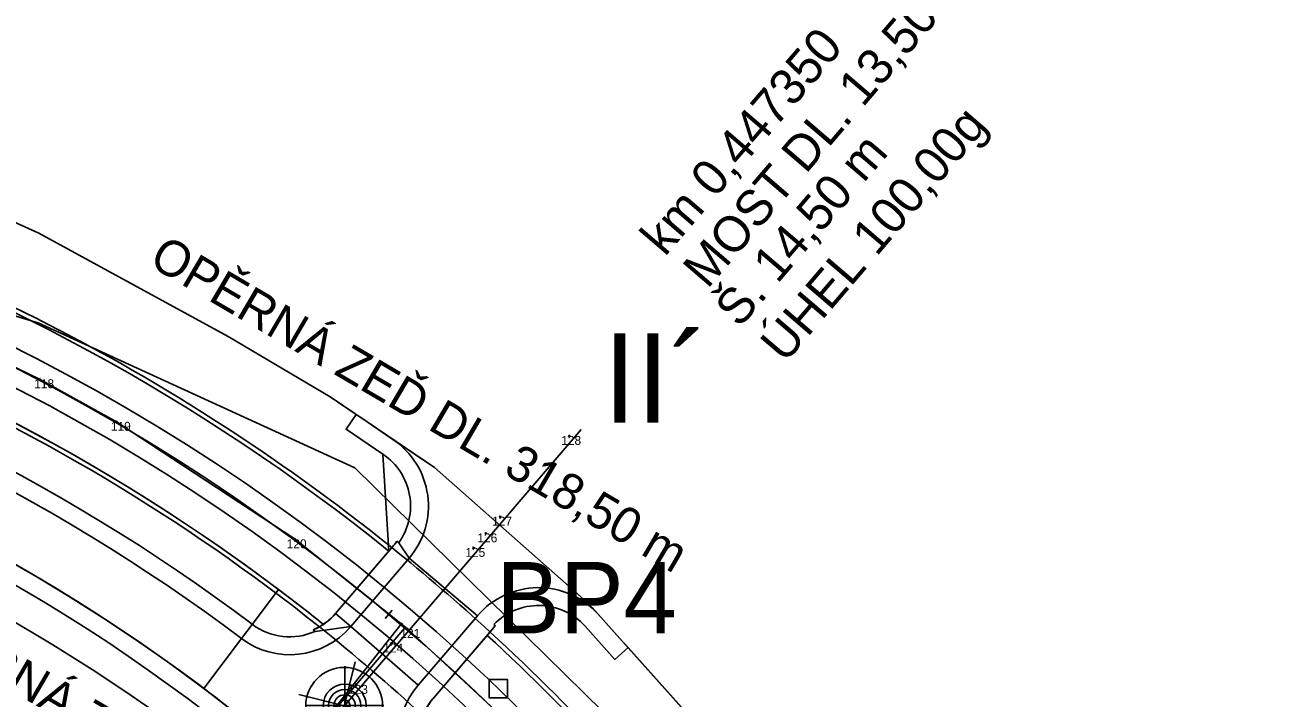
# Model space of a CAD drawing. Extents: x -606444 to -604546, y -1158114 to -1156869.
# Drawn here: x -605244.8 to -605105.4, y -1157184.6 to -1157109.2 of the extents above; entities that cross this region are included whole.
import ezdxf

# ---------------------------------------------------------------- set-up
doc = ezdxf.new("R2010")
doc.units = 0
for name, color, linetype in [('0_sondy', 7, 'Continuous'), ('B_CHOD', 7, 'Continuous'), ('B_TRAM', 7, 'Continuous'), ('B_VOZ', 7, 'Continuous'), ('B_ZELEN', 7, 'Continuous'), ('geofyzikální profily_předběžný GTP', 7, 'Continuous'), ('jádrové vrty_předběžný GTP', 7, 'Continuous'), ('korozní průzkum', 7, 'Continuous'), ('netisk', 7, 'Continuous'), ('netisk2', 7, 'Continuous'), ('NS_VB', 7, 'Continuous'), ('NS_VB_OBJ', 7, 'Continuous'), ('NS_VB_POP', 7, 'Continuous'), ('OSA', 7, 'Continuous'), ('OSAPOP', 7, 'Continuous'), ('podélný profil trasou tramvaje', 7, 'Continuous'), ('sondy současného průzkumu', 7, 'Continuous'), ('stabilitní profily_předběžný GTP', 7, 'Continuous')]:
    doc.layers.add(name, color=color, linetype=linetype)

# ---------------------------------------------------------------- blocks, each defined once
blk = doc.blocks.new('709')
for p, q in [((0, 2.2), (0, -2.2)), ((-2.2, 0), (2.2, 0))]:
    blk.add_line(p, q)
for radius in [1.2, 0.9, 0.6, 0.3]:
    blk.add_circle((0, 0), radius)
blk = doc.blocks.new('IG vrt podr')
at = {"layer": 'sondy současného průzkumu'}
for p, q in [((0.412, 1.649), (-0.418, -1.672)), ((-1.698, 0.422), (1.644, -0.408))]:
    blk.add_line(p, q, dxfattribs=at)
blk.add_circle((-0.002, 0.001), 1.434, dxfattribs=at)

msp = doc.modelspace()

# ---------------------------------------------------------------- linework, layer by layer
for p, q in [((-605243.13, -1157148.91), (-605243.23, -1157148.81)), ((-605243.13, -1157148.91), (-605243.23, -1157149.01)), ((-605243.13, -1157148.91), (-605243.03, -1157148.81)), ((-605243.13, -1157148.91), (-605243.03, -1157149.01)), ((-605234.53, -1157153.68), (-605234.63, -1157153.58)), ((-605234.53, -1157153.68), (-605234.63, -1157153.78)), ((-605234.53, -1157153.68), (-605234.43, -1157153.58)), ((-605234.53, -1157153.68), (-605234.43, -1157153.78)), ((-605183.79, -1157155.26), (-605183.89, -1157155.16)), ((-605183.79, -1157155.26), (-605183.69, -1157155.16)), ((-605183.79, -1157155.26), (-605183.89, -1157155.36)), ((-605183.79, -1157155.26), (-605183.69, -1157155.36)), ((-605191.53, -1157164.3), (-605191.63, -1157164.2)), ((-605191.53, -1157164.3), (-605191.63, -1157164.4)), ((-605191.53, -1157164.3), (-605191.43, -1157164.2)), ((-605191.53, -1157164.3), (-605191.43, -1157164.4)), ((-605193.15, -1157166.17), (-605193.25, -1157166.07)), ((-605193.15, -1157166.17), (-605193.25, -1157166.27)), ((-605193.15, -1157166.17), (-605193.05, -1157166.07)), ((-605193.15, -1157166.17), (-605193.05, -1157166.27)), ((-605214.51, -1157166.83), (-605214.61, -1157166.73)), ((-605214.51, -1157166.83), (-605214.61, -1157166.93)), ((-605214.51, -1157166.83), (-605214.41, -1157166.73)), ((-605214.51, -1157166.83), (-605214.41, -1157166.93)), ((-605194.53, -1157167.79), (-605194.63, -1157167.69)), ((-605194.53, -1157167.79), (-605194.43, -1157167.69)), ((-605194.53, -1157167.79), (-605194.63, -1157167.89)), ((-605194.53, -1157167.79), (-605194.43, -1157167.89)), ((-605201.93, -1157176.87), (-605202.03, -1157176.77)), ((-605201.93, -1157176.87), (-605202.03, -1157176.97)), ((-605201.93, -1157176.87), (-605201.83, -1157176.77)), ((-605201.93, -1157176.87), (-605201.83, -1157176.97)), ((-605203.73, -1157178.5), (-605203.83, -1157178.4)), ((-605203.73, -1157178.5), (-605203.83, -1157178.6)), ((-605203.73, -1157178.5), (-605203.63, -1157178.4)), ((-605203.73, -1157178.5), (-605203.63, -1157178.6)), ((-605207.68, -1157183.13), (-605207.78, -1157183.03)), ((-605207.68, -1157183.13), (-605207.58, -1157183.03)), ((-605207.68, -1157183.13), (-605207.78, -1157183.23)), ((-605207.68, -1157183.13), (-605207.58, -1157183.23))]:
    msp.add_line(p, q)
at = {"layer": 'B_CHOD'}
for points in [[(-605203.54, -1157155.64), (-605206.43, -1157153.69), (-605207.68, -1157152.85), (-605208.8, -1157154.51), (-605204.66, -1157157.3)], [(-605203.44, -1157167.49), (-605209.98, -1157175.14), (-605208.27, -1157176.6)], [(-605208.27, -1157176.6), (-605201.73, -1157168.96), (-605202.9, -1157167.21), (-605203.09, -1157167.05)], [(-605202.9, -1157167.21), (-605201.73, -1157168.96)], [(-605212.47, -1157176.97), (-605212.25, -1157177.14), (-605208.27, -1157176.6), (-605209.98, -1157175.14)], [(-605194.07, -1157175.39), (-605200.71, -1157183.15)], [(-605182.02, -1157176.56), (-605178.68, -1157180.28), (-605177.2, -1157178.94), (-605178.11, -1157177.92), (-605180.54, -1157175.22)], [(-605219.32, -1157176.35), (-605220.52, -1157177.94)], [(-605220.52, -1157177.94), (-605219.32, -1157176.35)], [(-605208.27, -1157176.6), (-605212.25, -1157177.14)], [(-605199, -1157184.61), (-605192.99, -1157177.59), (-605192.23, -1157176.7)], [(-605192.07, -1157176.52), (-605192.25, -1157176.35)]]:
    msp.add_lwpolyline(points, dxfattribs=at)
for centre, radius, start, end in [((-605345.26, -1157343.76), 209.5, 53.0471, 97.5799), ((-605345.26, -1157343.76), 207.5, 53.0471, 97.5799), ((-605345.26, -1157343.76), 200.5, 46.8415, 97.5799), ((-605345.26, -1157343.76), 198.5, 46.8415, 97.5799), ((-605208.57, -1157163.11), 9, 319.4626, 56.0176), ((-605208.57, -1157163.11), 7, 324.1224, 56.0176), ((-605208.57, -1157163.11), 6.75, 319.4626, 324.2325), ((-605187.23, -1157181.24), 9, 41.9382, 139.4626), ((-605187.23, -1157181.24), 7, 41.9382, 135.7827), ((-605215.1, -1157170.75), 6.75, 306.2266, 319.4658), ((-605215.11, -1157170.75), 9, 233.0471, 319.4626), ((-605215.11, -1157170.75), 7, 233.0471, 294.1), ((-605215.11, -1157170.75), 6.75, 292.9973, 306.2299), ((-605187.1, -1157181.08), 6.75, 137.3987, 139.4626), ((-605193.87, -1157189), 9, 139.4626, 225.6318)]:
    msp.add_arc(centre, radius, start, end, dxfattribs=at)
at = {"layer": 'B_TRAM'}
for p, q in [((-605209.98, -1157175.14), (-605203.99, -1157168.14)), ((-605192.99, -1157177.59), (-605199, -1157184.61))]:
    msp.add_line(p, q, dxfattribs=at)
for centre, radius, start, end in [((-605345.33, -1157343.85), 225.5, 51.1864, 92.2057), ((-605345.33, -1157343.85), 214.5, 51.3406, 92.204), ((-605215.1, -1157170.75), 6.75, 303.9373, 319.4658), ((-605345.33, -1157343.85), 225.5, 27.1946, 47.5015), ((-605193.87, -1157188.99), 6.75, 139.4591, 154.7431)]:
    msp.add_arc(centre, radius, start, end, dxfattribs=at)
at = {"layer": 'B_VOZ'}
for points in [[(-605180.54, -1157175.22), (-605181.54, -1157174.1), (-605198.87, -1157158.79), (-605203.54, -1157155.64)], [(-605203.54, -1157155.64), (-605203.54, -1157155.64)], [(-605201.73, -1157168.96), (-605208.27, -1157176.6), (-605200.71, -1157183.15), (-605194.07, -1157175.39), (-605201.73, -1157168.96)], [(-605201.73, -1157168.96), (-605194.07, -1157175.39)], [(-605200.71, -1157183.15), (-605208.27, -1157176.6)], [(-605220.52, -1157177.94), (-605224.73, -1157183.54)], [(-605224.73, -1157183.54), (-605220.52, -1157177.94)]]:
    msp.add_lwpolyline(points, dxfattribs=at)
for centre, radius, start, end in [((-605345.26, -1157343.76), 207.5, 53.0471, 97.5799), ((-605345.26, -1157343.76), 200.5, 53.0471, 97.5799), ((-605208.57, -1157163.11), 9, 319.4626, 56.0174), ((-605208.57, -1157163.11), 9, 56.0174, 56.0176), ((-605187.23, -1157181.24), 9, 41.9382, 139.4626), ((-605215.11, -1157170.75), 9, 233.0471, 319.4626), ((-605345.26, -1157343.76), 200.5, 45.6318, 53.0471), ((-605193.87, -1157189), 9, 139.4626, 225.6318)]:
    msp.add_arc(centre, radius, start, end, dxfattribs=at)
at = {"layer": 'B_ZELEN'}
for points in [[(-605203.99, -1157168.14), (-605204.66, -1157157.3), (-605208.8, -1157154.51), (-605207.68, -1157152.85), (-605210.59, -1157150.89), (-605221.99, -1157144.13), (-605243.23, -1157132.55), (-605253.62, -1157127.89), (-605260.44, -1157124.83), (-605265.07, -1157123.34), (-605269.63, -1157121.52), (-605278.31, -1157118.54), (-605290.81, -1157115.61), (-605306.23, -1157112.78), (-605315.84, -1157111.84), (-605328.25, -1157110.41), (-605344.82, -1157109.94), (-605357.9, -1157109.88), (-605354.01, -1157118.52)], [(-605204.66, -1157157.3), (-605203.99, -1157168.14), (-605203.44, -1157167.49)], [(-605203.09, -1157167.05), (-605202.9, -1157167.21)], [(-605216.38, -1157172.44), (-605219.32, -1157176.35)], [(-605219.32, -1157176.35), (-605216.38, -1157172.44)], [(-605212.25, -1157177.14), (-605212.47, -1157176.97)], [(-605192.23, -1157176.7), (-605192.99, -1157177.59)], [(-605192.25, -1157176.35), (-605192.07, -1157176.52)], [(-605144.76, -1157240.79), (-605133.95, -1157239.93), (-605143.53, -1157224.32), (-605151.31, -1157212.15), (-605159.56, -1157200.24), (-605168.04, -1157189.17), (-605177.2, -1157178.94), (-605178.68, -1157180.28), (-605182.02, -1157176.56)]]:
    msp.add_lwpolyline(points, dxfattribs=at)
for centre, radius, start, end in [((-605345.33, -1157343.85), 225.5, 51.1864, 92.2057), ((-605345.33, -1157343.85), 214.5, 53.0445, 92.204), ((-605345.26, -1157343.76), 209.5, 53.0471, 97.5799), ((-605345.26, -1157343.76), 198.5, 46.8415, 97.5799), ((-605345.97, -1157349.67), 200.33, 48.8336, 96.6948), ((-605208.57, -1157163.11), 7, 324.1224, 56.0176), ((-605208.57, -1157163.11), 6.75, 319.4626, 323.1301), ((-605208.57, -1157163.11), 6.75, 323.1301, 323.9726), ((-605208.57, -1157163.11), 6.75, 323.9726, 324.2325), ((-605345.33, -1157343.85), 214.5, 51.3406, 53.0445), ((-605187.23, -1157181.24), 7, 41.9382, 135.7827), ((-605215.11, -1157170.75), 7, 233.0471, 294.1), ((-605215.11, -1157170.75), 6.75, 292.9973, 303.9417), ((-605187.1, -1157181.08), 6.75, 137.3987, 139.4626), ((-605345.33, -1157343.85), 225.5, 27.1946, 47.5015)]:
    msp.add_arc(centre, radius, start, end, dxfattribs=at)
at = {"layer": 'geofyzikální profily_předběžný GTP'}
msp.add_lwpolyline([(-605670.78, -1157141.05), (-605656.02, -1157139.47), (-605613.88, -1157139.36), (-605584.8, -1157137.32), (-605531.41, -1157136.33), (-605491.56, -1157133.4), (-605482.07, -1157135.61), (-605438.78, -1157126.66), (-605383.23, -1157124.52), (-605352.34, -1157123.33), (-605321.95, -1157126), (-605284.14, -1157130.42), (-605243.3, -1157142.6), (-605207.83, -1157158.83), (-605179.98, -1157186.15), (-605165.29, -1157202.67), (-605149.23, -1157223.34), (-605135.07, -1157244.47), (-605115.92, -1157286.28), (-605103.22, -1157315.84), (-605095.33, -1157330.32), (-605036.97, -1157403.36), (-604999.08, -1157442.54), (-604970.8, -1157468.35)], dxfattribs=at)
at = {"layer": 'korozní průzkum'}
msp.add_lwpolyline([(-605192.77, -1157182.54), (-605190.69, -1157182.54), (-605190.69, -1157184.57), (-605192.77, -1157184.57)], close=True, dxfattribs=at)
at = {"layer": 'netisk'}
msp.add_line((-605202.52, -1157176.17), (-605211.11, -1157187.04), dxfattribs=at)
at = {"layer": 'netisk2'}
msp.add_line((-605211.04, -1157187.04), (-605202.23, -1157176.75), dxfattribs=at)
at = {"layer": 'NS_VB'}
for p, q in [((-605253.62, -1157127.89), (-605243.23, -1157132.55)), ((-605243.23, -1157132.55), (-605221.99, -1157144.13)), ((-605221.99, -1157144.13), (-605210.59, -1157150.89)), ((-605210.59, -1157150.89), (-605206.43, -1157153.69)), ((-605207.68, -1157152.85), (-605208.8, -1157154.51)), ((-605198.87, -1157158.79), (-605206.43, -1157153.69)), ((-605204.66, -1157157.3), (-605208.8, -1157154.51)), ((-605181.54, -1157174.1), (-605198.87, -1157158.79)), ((-605203.44, -1157167.49), (-605209.98, -1157175.14)), ((-605203.09, -1157167.05), (-605202.9, -1157167.21)), ((-605201.73, -1157168.96), (-605208.27, -1157176.6)), ((-605181.54, -1157174.1), (-605178.11, -1157177.92)), ((-605194.07, -1157175.39), (-605200.71, -1157183.15)), ((-605212.25, -1157177.14), (-605212.47, -1157176.97)), ((-605192.23, -1157176.7), (-605199, -1157184.61)), ((-605192.25, -1157176.35), (-605192.07, -1157176.52)), ((-605182.02, -1157176.56), (-605178.68, -1157180.28)), ((-605178.11, -1157177.92), (-605168.04, -1157189.17)), ((-605177.2, -1157178.94), (-605178.68, -1157180.28))]:
    msp.add_line(p, q, dxfattribs=at)
for centre, radius, start, end in [((-605345.33, -1157343.85), 225.5, 51.1864, 92.2057), ((-605345.33, -1157343.85), 214.5, 51.3406, 92.204), ((-605345.26, -1157343.76), 209.5, 53.0471, 97.5799), ((-605345.26, -1157343.76), 207.5, 53.0471, 97.5799), ((-605345.26, -1157343.76), 200.5, 16.4017, 97.5799), ((-605345.26, -1157343.76), 198.5, 46.8415, 97.5799), ((-605345.97, -1157349.67), 200.33, 48.8336, 96.6948), ((-605208.57, -1157163.11), 9, 319.4626, 56.0176), ((-605208.57, -1157163.11), 7, 324.1224, 56.0176), ((-605208.57, -1157163.11), 6.75, 319.4626, 324.2325), ((-605187.23, -1157181.24), 9, 41.9382, 139.4626), ((-605187.23, -1157181.24), 7, 41.9382, 135.7827), ((-605215.11, -1157170.75), 6.75, 292.9973, 319.4626), ((-605215.11, -1157170.75), 9, 233.0471, 319.4626), ((-605215.11, -1157170.75), 7, 233.0471, 294.1), ((-605187.1, -1157181.08), 6.75, 137.3987, 139.4626), ((-605345.33, -1157343.85), 225.5, 27.1946, 47.5015), ((-605193.87, -1157189), 9, 139.4626, 225.6318), ((-605193.87, -1157189), 6.75, 139.4626, 165.6816)]:
    msp.add_arc(centre, radius, start, end, dxfattribs=at)
at = {"layer": 'NS_VB_OBJ'}
for radius, start, end in [(226, 51.1826, 76.0474), (214, 51.3884, 82.5829), (226, 47.5059, 51.1826), (214, 47.2894, 51.3884), (226, 27.1946, 47.5059)]:
    msp.add_arc((-605345.33, -1157343.85), radius, start, end, dxfattribs=at)
at = {"layer": 'OSA'}
for radius, start, end in [(222, 27.1947, 92.2052), (220, 27.1948, 92.2049), (218, 27.1949, 92.2045)]:
    msp.add_arc((-605345.33, -1157343.85), radius, start, end, dxfattribs=at)
at = {"layer": 'OSAPOP'}
msp.add_line((-605204.4, -1157175.7), (-605203.63, -1157174.78), dxfattribs=at)
at = {"layer": 'podélný profil trasou tramvaje'}
msp.add_lwpolyline([(-605085.67, -1157373.96), (-605102.48, -1157348.99), (-605137.42, -1157269.35), (-605142.94, -1157257.48), (-605148.09, -1157246.14), (-605156.56, -1157230.62), (-605167.27, -1157214.45), (-605176.96, -1157202.08), (-605190.28, -1157187.63), (-605201.93, -1157176.87), (-605210.19, -1157170.25), (-605214.51, -1157166.83), (-605234.53, -1157153.68), (-605243.13, -1157148.91), (-605255.42, -1157142.97), (-605270.4, -1157136.88), (-605273.54, -1157135.89), (-605289.22, -1157131.03), (-605304.97, -1157127.5), (-605318.55, -1157125.25), (-605341.87, -1157123.88), (-605358.23, -1157124.22), (-605590.31, -1157143.82)], dxfattribs=at)
at = {"layer": 'stabilitní profily_předběžný GTP'}
msp.add_lwpolyline([(-605213.75, -1157191.02), (-605182.46, -1157154.53)], dxfattribs=at)

# ---------------------------------------------------------------- block references
at = {"layer": '0_sondy', "xscale": 2, "yscale": 2}
msp.add_blockref('709', (-605208.95, -1157185.44), dxfattribs=at)
at = {"layer": 'jádrové vrty_předběžný GTP', "xscale": 3, "yscale": 3}
msp.add_blockref('IG vrt podr', (-605209, -1157185.48), dxfattribs=at)

# ---------------------------------------------------------------- texts
for s, p in [('118', (-605243.74, -1157149.91)), ('119', (-605235.15, -1157154.68)), ('128', (-605184.69, -1157156.26)), ('127', (-605192.43, -1157165.3)), ('126', (-605194.08, -1157167.17)), ('120', (-605215.45, -1157167.83)), ('125', (-605195.43, -1157168.79)), ('121', (-605202.71, -1157177.87)), ('124', (-605204.63, -1157179.5)), ('123', (-605208.58, -1157184.13))]:
    msp.add_text(s, height=1).set_placement(p)
at = {"layer": 'korozní průzkum'}
msp.add_text('BP4', height=8, dxfattribs=at).set_placement((-605191.97, -1157177.37))
at = {"layer": 'NS_VB_POP'}
for s, rotation, p in [('MOST DL. 13,50 m', 49.4418, (-605168.3, -1157138.88)), ('km 0,447350', 49.4418, (-605173.07, -1157135.27)), ('ÚHEL 100,00g', 49.4418, (-605159.62, -1157147.22)), ('Š. 14,50 m', 49.4418, (-605164.72, -1157143.27)), ('OPĚRNÁ ZEĎ DL. 318,50 m', 329.5835, (-605231.04, -1157136.08)), ('OPĚRNÁ ZEĎ DL. 322,50 m', 329.5835, (-605259.99, -1157175.79))]:
    msp.add_text(s, height=4, rotation=rotation, dxfattribs=at).set_placement(p)
at = {"layer": 'stabilitní profily_předběžný GTP'}
msp.add_text('II´', height=10, dxfattribs=at).set_placement((-605179.99, -1157153.78))

doc.saveas('drawing.dxf')
